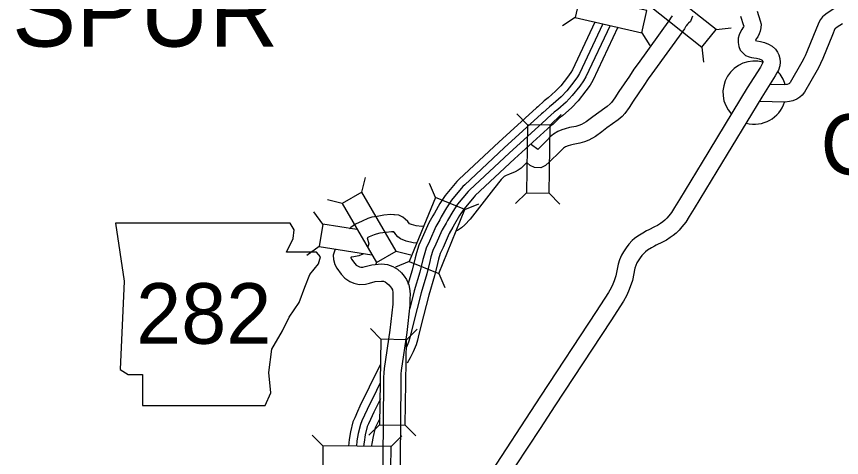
# Model space of a CAD drawing. Extents: x 535214 to 694517, y 381272 to 484355.
# Drawn here: x 552475 to 559659, y 472159 to 476004 of the extents above; entities that cross this region are included whole.
import ezdxf

# ---------------------------------------------------------------- set-up
doc = ezdxf.new("R2010")
doc.units = 0
for name, color, linetype in [('Level 11', 7, 'Continuous'), ('Level 15', 7, 'Continuous'), ('Level 19', 7, 'Continuous'), ('Level 20', 7, 'Continuous'), ('Level 21', 7, 'Continuous'), ('Level 24', 7, 'Continuous')]:
    doc.layers.add(name, color=color, linetype=linetype)

msp = doc.modelspace()

# ---------------------------------------------------------------- linework, layer by layer
at = {"layer": 'Level 11'}
for p, q in [((555766.4, 474275.4), (555762, 474275.6)), ((555752.2, 474126), (555756.6, 474125.7))]:
    msp.add_line(p, q, dxfattribs=at)
for points in [[(559667.1, 476119), (559637.8, 476101.3), (559584.4, 476065.9), (559535.4, 476033.2), (559509.2, 476013.4), (559495, 475999.7), (559475.9, 475978.2), (559465.9, 475956.7), (559441.7, 475900.8), (559357.9, 475694.1), (559343.2, 475660.2), (559334.5, 475644.6), (559314.6, 475605.8), (559213.5, 475428.9), (559207.8, 475421.5), (559205.9, 475419.9), (559201.7, 475417.1), (559186.8, 475411.6), (559179.5, 475409.4), (559164.1, 475408.1), (559038.6, 475411.3)], [(558361.4, 476007.7), (558356.1, 475990.6), (558344.2, 475959.9), (558327.2, 475945.8), (558319.7, 475936.4), (558306.9, 475922.2), (558303.1, 475917.8), (558300.7, 475914.1), (558290.7, 475894.8), (558008.4, 475504.2), (557975.6, 475460), (557937.6, 475400.9), (557845.5, 475265.6), (557809.1, 475208.8), (557771.7, 475157.2), (557749.4, 475133), (557713.1, 475101.9), (557616.1, 475031.7), (557571.9, 474998.2), (557516.4, 474958.3), (557459.7, 474926), (557421.2, 474911.5), (557380.6, 474898.4), (557322.5, 474889.1), (557298.1, 474882.2), (557277.6, 474875), (557256.3, 474866), (557237.8, 474855.2), (557226.2, 474845.2), (557205.2, 474822.8), (557117.4, 474735.8), (557081.3, 474705.6), (557042.4, 474685.6), (556986.4, 474686.4), (556947.8, 474704.7), (556920.8, 474726.9), (556917.5, 474729.3), (556895.2, 474707.2), (556870.6, 474681.4), (556845, 474663.4), (556818, 474650.6), (556768.1, 474630.1), (556738.5, 474617.4), (556721.4, 474607.4), (556709.8, 474598.4), (556703.7, 474592.7), (556695.1, 474582.2), (556629.6, 474497.2), (556425.9, 474235.7), (556380.4, 474186.4), (556349, 474160.3), (556315.5, 474139.2), (556306.4, 474134.9)], [(558183.5, 476008.8), (558171.2, 475990.3), (558162.5, 475973.5), (557887.3, 475592.8), (557852.1, 475545.3), (557812.4, 475483.7), (557720.4, 475348.3), (557685.1, 475293.4), (557655.4, 475252.4), (557645.2, 475241.2), (557620.1, 475219.8), (557526.8, 475152.2), (557482.9, 475118.9), (557435.3, 475084.8), (557395.7, 475062.2), (557371.6, 475053.1), (557345.5, 475044.7), (557290, 475035.9), (557252.7, 475025.2), (557223.5, 475015), (557189.1, 475000.4), (557150.1, 474977.7), (557122.1, 474953.4), (557097.7, 474927.4), (557016.4, 474846.8), (557013.8, 474844.6), (556960.7, 474884.8), (556956.8, 474886)], [(559667.5, 475941), (559622.3, 475910.8), (559606.8, 475899.1), (559603.2, 475895.7), (559602.7, 475895), (559580.1, 475842.9), (559496.2, 475636), (559477.8, 475593.6), (559466.8, 475573.9), (559446.5, 475534.4), (559338.5, 475345.3), (559317.6, 475318.4), (559297.7, 475300.8), (559270.2, 475282.4), (559234.4, 475269.3), (559207.8, 475261.2), (559168.4, 475258), (558943.5, 475263.7)], [(555762, 474275.6), (555734.9, 474276.6), (555673, 474270.4), (555614.6, 474261.4), (555569.1, 474252.9), (555534.6, 474241.5), (555484.4, 474219.5), (555427.3, 474194), (555386.8, 474165.4), (555375.8, 474152.8)], [(556024.3, 474174.7), (556005.9, 474174), (555954.8, 474178.9), (555913.7, 474189.6), (555895.9, 474196.1), (555882.8, 474216.1), (555861, 474237.5), (555838.8, 474253.7), (555805.4, 474271.6), (555766.4, 474275.4)], [(555756.6, 474125.7), (555739.7, 474126.4), (555691.9, 474121.6), (555639.8, 474113.5), (555606.6, 474107.3), (555588.4, 474101.3), (555545.1, 474082.4), (555529, 474075.2), (555543.6, 474020.8), (555531.8, 473987.8)], [(555963.7, 474027.4), (555928.8, 474030.7), (555868.9, 474046.2), (555818.7, 474064.7), (555795, 474081.8), (555777.6, 474102.9), (555766.1, 474120.5), (555763.7, 474122.8), (555760.4, 474125.3), (555752.2, 474126)], [(555250.7, 473971.4), (555242.9, 473958.2), (555233.6, 473922.9), (555235, 473884.5), (555247.1, 473842.9), (555265.9, 473808.2), (555302.8, 473757), (555333.9, 473722.1), (555378.5, 473693.4), (555413, 473678.8), (555458.5, 473667.6), (555513.3, 473669.6), (555548.6, 473678.5), (555597.9, 473692), (555652.3, 473697.3), (555670.7, 473695.3), (555685.3, 473689.9), (555701.3, 473680.2), (555717.3, 473665.4), (555732, 473647.2), (555740.7, 473635.3), (555747.9, 473619.6), (555752.2, 473596.8), (555753.3, 473579.5), (555751.3, 473556.2), (555750.9, 473495.4), (555726.7, 473268), (555675.7, 472934.1), (555673.3, 472897.9), (555671.5, 472856), (555671.9, 472815.6)], [(555494.1, 473936.8), (555490.3, 473932.9), (555454.9, 473916.7), (555412, 473908.6), (555395.9, 473906.9), (555389.8, 473904.1), (555386.2, 473901.6), (555386.6, 473900.2), (555393.2, 473888.2), (555420, 473851), (555432.3, 473837.2), (555448.9, 473826.5), (555460.5, 473821.6), (555473.9, 473818.3), (555492, 473818.9), (555510.5, 473823.5), (555570.6, 473840), (555652.8, 473848), (555705.3, 473842.6), (555750.8, 473825.5), (555792, 473800.7), (555827.3, 473768), (555851, 473738.5), (555870.6, 473711.7), (555891.9, 473665.6), (555901.3, 473615.5), (555903.7, 473577.8), (555901.2, 473549.2), (555900.8, 473486.9), (555875.5, 473248.7), (555825, 472917.6), (555823.1, 472889.7), (555821.5, 472853.6), (555821.9, 472817)], [(555671.9, 472817.1), (555664.7, 472146.8), (555653.8, 470819.8), (555651.7, 470565.2)], [(555821.9, 472815.5), (555814.7, 472145.4), (555804.1, 470860.1)]]:
    msp.add_lwpolyline(points, dxfattribs=at)
at = {"layer": 'Level 15'}
for points in [[(558924.6, 476048.7), (558951.1, 475966.5), (558959, 475936.2), (558958.1, 475903.8), (558951.4, 475875.6), (558942.5, 475851.9), (558930.2, 475827.3), (558917.3, 475808.5), (558914.4, 475803.5), (558911.1, 475795.7), (558910.5, 475793.3), (558922.9, 475791), (558953.9, 475785.2), (558989.8, 475775.5), (559023.9, 475761.5), (559056.8, 475745.4), (559083.4, 475718.3), (559102.3, 475692.2), (559112.3, 475669.9), (559123.7, 475637.4), (559125, 475606.4), (559122.7, 475574.9), (559110.1, 475536.5), (559097.4, 475512.5), (559082.8, 475486.4), (558966.5, 475301.7), (558573.3, 474656.5), (558376.4, 474330.8), (558333.4, 474259.5), (558302.4, 474209.7), (558270, 474168.6), (558245.3, 474140.4), (558219, 474115.5), (558194, 474095.7), (558167.8, 474075.8), (558134, 474054.1), (558100.8, 474035.7), (558045.9, 474009.1), (558031, 474002.1), (558004.8, 473986.9), (557970.6, 473966), (557953.2, 473952.7), (557942.6, 473943), (557921.3, 473920.8), (557905.3, 473900.1), (557887.7, 473873.3), (557876.9, 473855), (557867.7, 473833.2), (557861, 473808.2), (557839, 473702.3), (557820.2, 473646.3), (557804.4, 473608.7), (557786.1, 473569.5), (557759.6, 473521.3), (557649.4, 473350.3), (557163.8, 472610.6), (557034.5, 472411.9), (556821.5, 472086.8)], [(558781.1, 476005), (558807, 475924.6), (558808, 475920.9), (558807.7, 475919.6), (558804.9, 475912.1), (558800.6, 475903.6), (558790.8, 475889.2), (558780, 475871), (558768.6, 475843.7), (558760.9, 475814.1), (558759.5, 475776.3), (558765.2, 475742.3), (558777.3, 475710.8), (558798.7, 475686.5), (558822.6, 475665), (558855.8, 475650.5), (558875.7, 475647.2), (558895.4, 475643.6), (558920.4, 475638.9), (558941.6, 475633.1), (558962.5, 475624.6), (558967.7, 475622), (558968.4, 475621.4), (558971.7, 475616.7), (558972.9, 475614.1), (558974.8, 475608.8), (558974.5, 475604.2), (558971.6, 475595.5), (558965.7, 475584.3), (558953.8, 475563.1), (558839, 475380.7), (558445.1, 474734.3), (558248, 474408.3), (558205.5, 474337.8), (558179.5, 474296), (558154.7, 474264.6), (558137, 474244.4), (558120.7, 474228.9), (558102.1, 474214.3), (558081.8, 474198.8), (558057, 474182.9), (558031.7, 474168.8), (557981.3, 474144.5), (557961.4, 474135.1), (557928.1, 474115.8), (557885.9, 474090), (557856.8, 474067.8), (557837.7, 474050.3), (557807.5, 474018.9), (557783.1, 473987.2), (557760.4, 473952.7), (557742.7, 473922.7), (557725.6, 473882.3), (557715, 473843.1), (557694, 473741.5), (557679.8, 473699.3), (557667.3, 473669.5), (557652.3, 473637.4), (557630.7, 473598.2), (557523.6, 473432.1), (557038.3, 472692.6), (556908.9, 472493.9), (556696, 472168.9), (556290.7, 471549.1)]]:
    msp.add_lwpolyline(points, dxfattribs=at)
at = {"layer": 'Level 19'}
for points in [[(557643.5, 475925.2), (557433.3, 475476.8), (557413.4, 475443.9), (557379.3, 475396), (557313.4, 475313.4), (557260.8, 475257.1), (557188.7, 475193.9), (557156.8, 475168.6), (557099.9, 475116.2), (557086.4, 475105.9), (556764.9, 474812.8), (556422.2, 474492.7), (556408.6, 474478.6), (556314.7, 474366.1), (556274, 474304.1), (556228.8, 474225.9), (556215.5, 474200.5), (556181.7, 474144.2), (556127.4, 474018.3), (556100.8, 473962.8), (556084.3, 473907), (556073.6, 473868.3), (556048.1, 473759), (555999.1, 473594), (555928.8, 473320.3), (555906.5, 473224.4), (555900.9, 473201), (555889.8, 473165.5), (555871.5, 473120.4)], [(557712.1, 475909.6), (557494, 475444.3), (557470.9, 475406.1), (557434.2, 475354.6), (557365.5, 475268.4), (557308.8, 475207.7), (557232.7, 475141), (557201.5, 475116.3), (557144.1, 475063.4), (557130.4, 475053), (556811.5, 474762.3), (556470.5, 474443.6), (556459.8, 474432.6), (556370, 474325.1), (556332.5, 474268), (556289.1, 474192.8), (556275.5, 474166.8), (556243, 474112.8), (556190, 473989.9), (556165.2, 473938.1), (556150.4, 473888.1), (556140.2, 473851.3), (556114.6, 473741.4), (556065.4, 473575.6), (555995.6, 473304), (555973.4, 473208.7), (555967.3, 473182.8), (555954.5, 473142.2), (555929.5, 473080.3), (555902.3, 473026.7), (555877.1, 472981.2)], [(557512.5, 475955), (557317.5, 475538.8), (557303.7, 475516), (557274.5, 475475), (557214, 475399.2), (557169.4, 475351.5), (557104.7, 475294.7), (557071.5, 475268.5), (557015.6, 475216.9), (557002.3, 475206.8), (556675.9, 474909.3), (556330.2, 474586.3), (556310.9, 474566.3), (556209.1, 474444.4), (556162.2, 474373), (556113.8, 474289.2), (556101, 474264.8), (556064.7, 474204.3), (556007.9, 474072.7), (555977.8, 474010), (555958.1, 473943), (555946.4, 473900.8), (555921.2, 473792.6), (555884.2, 473667.9)], [(557581.1, 475939.4), (557378.2, 475506.3), (557361.2, 475478.2), (557329.4, 475433.6), (557266.1, 475354.3), (557217.3, 475302.1), (557148.7, 475241.9), (557116.2, 475216.2), (557059.8, 475164.1), (557046.4, 475154), (556722.5, 474858.8), (556378.4, 474537.2), (556362.1, 474520.4), (556264.4, 474403.4), (556220.8, 474336.9), (556174.1, 474256.1), (556161, 474231.1), (556125.9, 474172.8), (556070.5, 474044.2), (556042.2, 473985.3), (556024.2, 473924.1), (556013, 473883.8), (555987.7, 473775), (555938.9, 473610.6), (555899.5, 473457.2)], [(555645, 472973.8), (555547.5, 472772.6), (555465.2, 472606.7), (555443.1, 472558.9)], [(555638.9, 472803.5), (555609.2, 472742.3), (555528.1, 472578.8), (555504.6, 472527.5)], [(555643.4, 472670.6), (555585.3, 472553.4), (555558.1, 472491)], [(555443.1, 472558.9), (555420.5, 472506.2), (555405, 472469.5), (555384, 472382.3), (555372.2, 472315.5)], [(555504.6, 472527.5), (555483, 472477.6), (555470.5, 472447.9), (555451.4, 472368.2), (555439.9, 472303.5)], [(555558.1, 472491), (555539.9, 472451.6), (555530.1, 472428.3), (555512.6, 472355.5), (555501.4, 472292.6)], [(555637.8, 472497.8), (555602.4, 472422.9), (555595.6, 472406.8), (555579.9, 472341.4), (555569.1, 472280.6)], [(555372.2, 472315.5), (555365.7, 472257.1)], [(555439.6, 472301.3), (555435.2, 472260)], [(555501.7, 472294.7), (555497.4, 472254.2)], [(555570.1, 472287.4), (555566.8, 472256.7)]]:
    msp.add_lwpolyline(points, dxfattribs=at)
at = {"layer": 'Level 20'}
for p, q in [((557340.5, 475994), (557228.9, 475923.6)), ((558566.8, 475890.1), (558698, 475904.9)), ((557919.8, 475862.5), (557990.2, 475750.8)), ((558443.3, 475735.3), (558458.1, 475604.2)), ((556924.2, 475059.4), (556832.2, 475154.1)), ((557122.2, 475056.5), (557216.9, 475148.4)), ((555481.4, 474471.6), (555515, 474599.2)), ((556122.7, 474425), (556071.4, 474546.7)), ((555481.4, 474471.6), (555310.3, 474371.9)), ((555780.5, 473958.4), (555481.4, 474471.6)), ((556915.5, 474465.5), (556820.8, 474373.5)), ((557113.4, 474462.5), (557205.4, 474367.8)), ((555310.3, 474371.9), (555182.7, 474405.5)), ((555310.3, 474371.9), (555609.4, 473858.7)), ((556380.4, 474320), (556502, 474371.2)), ((555142.7, 474193.8), (555065.3, 474300.7)), ((555142.7, 474193.8), (555111.4, 473998.2)), ((555439.2, 474146.3), (555142.7, 474193.8)), ((555111.4, 473998.2), (555004.4, 473920.8)), ((555111.4, 473998.2), (555569.9, 473924.8)), ((555609.4, 473858.7), (555780.5, 473958.4)), ((555780.5, 473958.4), (555908.1, 473924.7)), ((555609.4, 473858.7), (555605.5, 473843.9)), ((555895.8, 473868.4), (555774.2, 473817.2)), ((556153.5, 473763.4), (556204.7, 473641.8)), ((555648.4, 473189.2), (555556.4, 473283.9)), ((555870.3, 473185.9), (555965, 473277.8)), ((555637.4, 472444.4), (555542.7, 472352.5)), ((555859.4, 472441.2), (555951.3, 472346.5)), ((555143.3, 472260), (555050.7, 472354.1)), ((555737.3, 472255.3), (555831.4, 472347.9))]:
    msp.add_line(p, q, dxfattribs=at)
for points in [[(557978.9, 476105.7), (558443.3, 475735.3), (558566.8, 475890.1), (558102.4, 476260.5)], [(557340.5, 475994), (557919.8, 475862.5), (557963.6, 476055.6), (557384.4, 476187.1)], [(556924.2, 475059.4), (556915.5, 474465.5), (557113.4, 474462.5), (557122.2, 475056.5)], [(556153.5, 473763.4), (556380.4, 474320), (556122.7, 474425), (555895.8, 473868.4)], [(555648.4, 473189.2), (555637.4, 472444.4), (555859.4, 472441.2), (555870.3, 473185.9)], [(555141.8, 472062), (555735.7, 472057.3), (555737.3, 472255.3), (555143.3, 472260)]]:
    msp.add_lwpolyline(points, close=True, dxfattribs=at)
at = {"layer": 'Level 21'}
msp.add_lwpolyline([(553336.6, 474203.2), (553412.7, 473695.6), (553378.9, 472925.9), (553446.6, 472883.6), (553573.5, 472883.6), (553573.5, 472612.9), (554639.3, 472612.9), (554690, 472722.9), (554673.1, 472900.5), (554698.5, 473103.5), (554791.6, 473264.2), (554850.8, 473382.7), (554935.4, 473509.5), (554986.1, 473644.9), (555028.4, 473754.9), (555104.5, 473847.9), (555121.5, 473907.1), (555087.6, 473949.4), (554825.4, 473949.4), (554884.6, 474067.8), (554893.1, 474144), (554858, 474202.4)], close=True, dxfattribs=at)
at = {"layer": 'Level 24'}
for start, end in [(74.59118, 222.75872), (15.08937, 42.6803), (254.74173, 342.67169)]:
    msp.add_arc((558901.9, 475339.8), 275, start, end, dxfattribs=at)

# ---------------------------------------------------------------- texts
at = {"layer": 'Level 21'}
for s, height, p in [('SPUR', 623.56, (552437, 475741.2)), ('282', 528, (553516.4, 473150.7))]:
    msp.add_text(s, height=height, dxfattribs=at).set_placement(p)
at = {"layer": 'Level 24'}
msp.add_text('Cain', height=528, dxfattribs=at).set_placement((559477.3, 474625.5))

doc.saveas('drawing.dxf')
